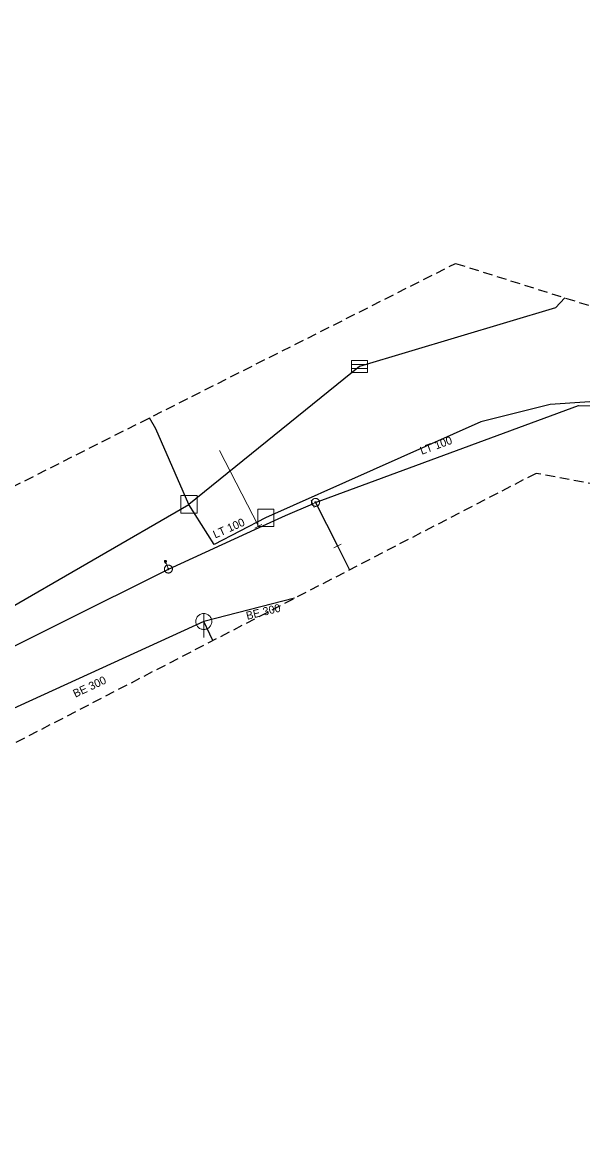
# Model space of a CAD drawing. Extents: x -688691 to -688449, y -974248 to -973966.
# Drawn here: x -688619.4 to -688549.3, y -974104.2 to -973965.6 of the extents above; entities that cross this region are included whole.
import ezdxf

# ---------------------------------------------------------------- set-up
doc = ezdxf.new("R2010")
doc.units = 0
doc.header["$LTSCALE"] = 0.4
doc.linetypes.add('MEDIUM_DASHED', pattern=[4.5, 3, -1.5])
for name, color, linetype, lineweight in [('1', 7, 'MEDIUM_DASHED', 25), ('13', 7, 'Continuous', 13), ('14', 7, 'Continuous', 25), ('17', 7, 'Continuous', 25), ('22', 7, 'Continuous', 13), ('34', 7, 'Continuous', 13), ('47', 7, 'Continuous', 13), ('9', 7, 'Continuous', 13)]:
    doc.layers.add(name, color=color, linetype=linetype, lineweight=lineweight)

msp = doc.modelspace()

# ---------------------------------------------------------------- linework, layer by layer
at = {"layer": '1'}
msp.add_lwpolyline([(-688492.642, -974007.422), (-688474.778, -973965.553), (-688449.099, -973975.602), (-688472.545, -974030.309), (-688492.642, -974033.659), (-688555.165, -974021.936), (-688650.066, -974071.061), (-688624.387, -974128.002), (-688613.222, -974120.745), (-688593.125, -974162.055), (-688604.29, -974165.404), (-688581.96, -974212.855), (-688565.213, -974206.156), (-688558.514, -974230.719), (-688607.64, -974248.024), (-688622.154, -974231.277), (-688607.64, -974225.136), (-688626.62, -974194.433), (-688691.376, -974059.338), (-688565.213, -973995.698), (-688544, -974002.397)], close=True, dxfattribs=at)
at = {"layer": '13'}
msp.add_line((-688589.863, -974028.551), (-688594.744, -974019.082), dxfattribs=at)
at = {"layer": '14'}
for p, q in [((-688577.23, -974008.592), (-688598.575, -974025.813)), ((-688658.556, -974060.52), (-688598.575, -974025.813)), ((-688585.339, -974037.555), (-688596.688, -974040.453)), ((-688596.688, -974040.453), (-688625, -974053.399)), ((-688595.545, -974042.839), (-688596.688, -974040.453))]:
    msp.add_line(p, q, dxfattribs=at)
at = {"layer": '14', "lineweight": 13}
for p, q in [((-688583.081, -974025.74), (-688582.724, -974025.561)), ((-688589.78, -974028.709), (-688589.863, -974028.551)), ((-688601.114, -974033.895), (-688601.489, -974032.939))]:
    msp.add_line(p, q, dxfattribs=at)
at = {"layer": '14'}
for points in [[(-688551.583, -974000.003), (-688552.727, -974001.266), (-688577.23, -974008.592)], [(-688544.118, -974012.713), (-688553.402, -974013.335), (-688562.069, -974015.498), (-688588.977, -974027.483)], [(-688598.575, -974025.813), (-688602.697, -974016.388), (-688603.455, -974014.989)], [(-688588.977, -974027.483), (-688595.407, -974030.817), (-688598.575, -974025.813)]]:
    msp.add_lwpolyline(points, dxfattribs=at)
at = {"layer": '17'}
for p, q in [((-688582.724, -974025.561), (-688579.989, -974031.009)), ((-688579.989, -974031.009), (-688578.486, -974034.008))]:
    msp.add_line(p, q, dxfattribs=at)
for points in [[(-688582.724, -974025.561), (-688549.875, -974013.454), (-688546.964, -974013.527)], [(-688601.114, -974033.895), (-688589.78, -974028.709), (-688586.478, -974027.199), (-688583.081, -974025.74)], [(-688652.327, -974058.754), (-688641.42, -974053.987), (-688601.114, -974033.895)]]:
    msp.add_lwpolyline(points, dxfattribs=at)
at = {"layer": '22'}
for p, q in [((-688578.241, -974008.335), (-688576.241, -974008.335)), ((-688578.241, -974008.835), (-688576.241, -974008.835)), ((-688596.688, -974042.453), (-688596.687, -974039.453))]:
    msp.add_line(p, q, dxfattribs=at)
for points in [[(-688578.241, -974007.835), (-688576.241, -974007.835), (-688576.241, -974009.335), (-688578.241, -974009.335)], [(-688599.554, -974024.723), (-688597.522, -974024.723), (-688597.522, -974026.916), (-688599.554, -974026.916)], [(-688589.956, -974026.393), (-688587.924, -974026.393), (-688587.924, -974028.586), (-688589.956, -974028.586)], [(-688595.688, -974040.453), (-688595.693, -974040.344), (-688595.711, -974040.236), (-688595.741, -974040.13), (-688595.781, -974040.029), (-688595.833, -974039.932), (-688595.895, -974039.842), (-688595.967, -974039.759), (-688596.047, -974039.685), (-688596.135, -974039.619), (-688596.229, -974039.564), (-688596.329, -974039.519), (-688596.434, -974039.486), (-688596.541, -974039.464), (-688596.65, -974039.454), (-688596.76, -974039.456), (-688596.868, -974039.47), (-688596.975, -974039.495), (-688597.078, -974039.532), (-688597.176, -974039.581), (-688597.268, -974039.639), (-688597.354, -974039.708), (-688597.431, -974039.785), (-688597.5, -974039.871), (-688597.559, -974039.963), (-688597.607, -974040.061), (-688597.644, -974040.164), (-688597.67, -974040.271), (-688597.684, -974040.379), (-688597.687, -974040.489), (-688597.677, -974040.598), (-688597.656, -974040.705), (-688597.622, -974040.809), (-688597.578, -974040.909), (-688597.523, -974041.004), (-688597.457, -974041.092), (-688597.383, -974041.172), (-688597.3, -974041.244), (-688597.21, -974041.306), (-688597.114, -974041.358), (-688597.012, -974041.399), (-688596.907, -974041.429), (-688596.799, -974041.447), (-688596.689, -974041.453), (-688596.58, -974041.447), (-688596.472, -974041.429), (-688596.367, -974041.4), (-688596.265, -974041.359), (-688596.168, -974041.307), (-688596.078, -974041.245), (-688595.995, -974041.174), (-688595.92, -974041.094), (-688595.855, -974041.006), (-688595.799, -974040.912), (-688595.755, -974040.812), (-688595.721, -974040.708), (-688595.699, -974040.6), (-688595.689, -974040.491)]]:
    msp.add_lwpolyline(points, close=True, dxfattribs=at)
at = {"layer": '34'}
for p, q in [((-688583.28, -974025.281), (-688582.882, -974026.198)), ((-688590.305, -974028.783), (-688589.419, -974028.319)), ((-688579.542, -974030.784), (-688580.436, -974031.232))]:
    msp.add_line(p, q, dxfattribs=at)
at = {"layer": '47'}
for points in [[(-688582.265, -974025.361), (-688582.288, -974025.315), (-688582.316, -974025.27), (-688582.349, -974025.23), (-688582.385, -974025.192), (-688582.426, -974025.159), (-688582.47, -974025.13), (-688582.516, -974025.106), (-688582.565, -974025.087), (-688582.615, -974025.073), (-688582.667, -974025.064), (-688582.719, -974025.06), (-688582.771, -974025.063), (-688582.823, -974025.071), (-688582.874, -974025.084), (-688582.923, -974025.102), (-688582.969, -974025.125), (-688583.014, -974025.153), (-688583.055, -974025.186), (-688583.092, -974025.222), (-688583.125, -974025.263), (-688583.154, -974025.307), (-688583.178, -974025.354), (-688583.198, -974025.402), (-688583.212, -974025.452), (-688583.22, -974025.504), (-688583.224, -974025.556), (-688583.221, -974025.609), (-688583.213, -974025.66), (-688583.2, -974025.711), (-688583.182, -974025.76), (-688583.159, -974025.806), (-688583.131, -974025.851), (-688583.098, -974025.892), (-688583.062, -974025.929), (-688583.021, -974025.962), (-688582.978, -974025.991), (-688582.931, -974026.016), (-688582.883, -974026.035), (-688582.832, -974026.049), (-688582.78, -974026.057), (-688582.728, -974026.061), (-688582.676, -974026.059), (-688582.624, -974026.05), (-688582.573, -974026.037), (-688582.524, -974026.019), (-688582.478, -974025.996), (-688582.433, -974025.968), (-688582.393, -974025.936), (-688582.355, -974025.899), (-688582.322, -974025.858), (-688582.293, -974025.815), (-688582.269, -974025.769), (-688582.25, -974025.72), (-688582.236, -974025.669), (-688582.227, -974025.617), (-688582.223, -974025.565), (-688582.226, -974025.514), (-688582.234, -974025.461), (-688582.247, -974025.41)], [(-688582.648, -974025.528), (-688582.652, -974025.52), (-688582.657, -974025.513), (-688582.662, -974025.507), (-688582.668, -974025.5), (-688582.675, -974025.495), (-688582.682, -974025.49), (-688582.689, -974025.486), (-688582.697, -974025.483), (-688582.706, -974025.481), (-688582.714, -974025.479), (-688582.723, -974025.479), (-688582.732, -974025.479), (-688582.74, -974025.48), (-688582.748, -974025.482), (-688582.756, -974025.485), (-688582.764, -974025.489), (-688582.771, -974025.494), (-688582.777, -974025.499), (-688582.784, -974025.505), (-688582.789, -974025.512), (-688582.794, -974025.519), (-688582.798, -974025.526), (-688582.801, -974025.534), (-688582.804, -974025.543), (-688582.805, -974025.551), (-688582.805, -974025.56), (-688582.805, -974025.569), (-688582.804, -974025.577), (-688582.802, -974025.585), (-688582.799, -974025.593), (-688582.795, -974025.601), (-688582.79, -974025.608), (-688582.785, -974025.614), (-688582.779, -974025.621), (-688582.772, -974025.626), (-688582.766, -974025.631), (-688582.758, -974025.635), (-688582.75, -974025.638), (-688582.741, -974025.641), (-688582.733, -974025.642), (-688582.724, -974025.642), (-688582.715, -974025.642), (-688582.707, -974025.641), (-688582.699, -974025.639), (-688582.691, -974025.636), (-688582.683, -974025.632), (-688582.676, -974025.627), (-688582.67, -974025.622), (-688582.663, -974025.616), (-688582.658, -974025.609), (-688582.653, -974025.603), (-688582.649, -974025.595), (-688582.646, -974025.587), (-688582.644, -974025.578), (-688582.642, -974025.57), (-688582.642, -974025.561), (-688582.642, -974025.552), (-688582.643, -974025.544), (-688582.645, -974025.536)], [(-688600.662, -974033.679), (-688600.688, -974033.633), (-688600.717, -974033.59), (-688600.751, -974033.551), (-688600.789, -974033.514), (-688600.831, -974033.482), (-688600.876, -974033.455), (-688600.923, -974033.433), (-688600.972, -974033.416), (-688601.023, -974033.403), (-688601.075, -974033.396), (-688601.127, -974033.395), (-688601.179, -974033.4), (-688601.231, -974033.408), (-688601.281, -974033.424), (-688601.329, -974033.443), (-688601.375, -974033.469), (-688601.418, -974033.498), (-688601.458, -974033.533), (-688601.494, -974033.57), (-688601.526, -974033.612), (-688601.553, -974033.657), (-688601.576, -974033.704), (-688601.593, -974033.754), (-688601.606, -974033.804), (-688601.612, -974033.856), (-688601.613, -974033.908), (-688601.609, -974033.961), (-688601.6, -974034.012), (-688601.584, -974034.062), (-688601.565, -974034.11), (-688601.539, -974034.156), (-688601.51, -974034.199), (-688601.476, -974034.24), (-688601.438, -974034.275), (-688601.396, -974034.307), (-688601.352, -974034.334), (-688601.305, -974034.357), (-688601.255, -974034.375), (-688601.204, -974034.387), (-688601.152, -974034.393), (-688601.1, -974034.394), (-688601.048, -974034.391), (-688600.996, -974034.381), (-688600.946, -974034.365), (-688600.898, -974034.346), (-688600.852, -974034.32), (-688600.809, -974034.291), (-688600.769, -974034.258), (-688600.733, -974034.219), (-688600.701, -974034.177), (-688600.674, -974034.133), (-688600.652, -974034.086), (-688600.634, -974034.037), (-688600.622, -974033.985), (-688600.615, -974033.933), (-688600.614, -974033.881), (-688600.618, -974033.829), (-688600.627, -974033.777), (-688600.643, -974033.727)], [(-688601.04, -974033.859), (-688601.043, -974033.851), (-688601.049, -974033.845), (-688601.054, -974033.838), (-688601.06, -974033.832), (-688601.067, -974033.827), (-688601.075, -974033.823), (-688601.082, -974033.819), (-688601.09, -974033.816), (-688601.099, -974033.814), (-688601.107, -974033.813), (-688601.116, -974033.813), (-688601.125, -974033.813), (-688601.133, -974033.815), (-688601.141, -974033.817), (-688601.149, -974033.821), (-688601.157, -974033.824), (-688601.163, -974033.83), (-688601.17, -974033.835), (-688601.176, -974033.841), (-688601.181, -974033.848), (-688601.185, -974033.856), (-688601.189, -974033.863), (-688601.192, -974033.871), (-688601.195, -974033.88), (-688601.195, -974033.888), (-688601.195, -974033.897), (-688601.195, -974033.906), (-688601.193, -974033.914), (-688601.191, -974033.922), (-688601.187, -974033.93), (-688601.184, -974033.938), (-688601.178, -974033.944), (-688601.173, -974033.951), (-688601.167, -974033.957), (-688601.16, -974033.962), (-688601.153, -974033.967), (-688601.145, -974033.97), (-688601.137, -974033.973), (-688601.128, -974033.976), (-688601.12, -974033.976), (-688601.111, -974033.976), (-688601.102, -974033.976), (-688601.094, -974033.974), (-688601.086, -974033.972), (-688601.078, -974033.968), (-688601.07, -974033.965), (-688601.064, -974033.959), (-688601.057, -974033.954), (-688601.051, -974033.948), (-688601.046, -974033.941), (-688601.041, -974033.934), (-688601.038, -974033.926), (-688601.035, -974033.918), (-688601.033, -974033.909), (-688601.032, -974033.901), (-688601.032, -974033.892), (-688601.032, -974033.883), (-688601.034, -974033.875), (-688601.036, -974033.867)]]:
    msp.add_lwpolyline(points, close=True, dxfattribs=at)
at = {"layer": '9'}
msp.add_line((-688601.49, -974033.066), (-688601.49, -974033.191), dxfattribs=at)
for points in [[(-688601.616, -974032.938), (-688601.615, -974032.951), (-688601.613, -974032.964), (-688601.61, -974032.977), (-688601.605, -974032.989), (-688601.599, -974033.001), (-688601.592, -974033.012), (-688601.584, -974033.022), (-688601.574, -974033.032), (-688601.564, -974033.04), (-688601.553, -974033.047), (-688601.541, -974033.053), (-688601.529, -974033.058), (-688601.516, -974033.061), (-688601.503, -974033.063), (-688601.49, -974033.066), (-688601.477, -974033.065), (-688601.464, -974033.063), (-688601.451, -974033.06), (-688601.439, -974033.055), (-688601.427, -974033.049), (-688601.416, -974033.042), (-688601.406, -974033.034), (-688601.396, -974033.024), (-688601.388, -974033.014), (-688601.381, -974033.003), (-688601.375, -974032.991), (-688601.37, -974032.979), (-688601.367, -974032.966), (-688601.365, -974032.953), (-688601.363, -974032.94), (-688601.364, -974032.927), (-688601.366, -974032.914), (-688601.369, -974032.901), (-688601.374, -974032.889), (-688601.38, -974032.877), (-688601.387, -974032.866), (-688601.395, -974032.856), (-688601.405, -974032.846), (-688601.415, -974032.838), (-688601.426, -974032.831), (-688601.438, -974032.825), (-688601.45, -974032.82), (-688601.463, -974032.817), (-688601.476, -974032.815), (-688601.489, -974032.813), (-688601.502, -974032.813), (-688601.515, -974032.815), (-688601.528, -974032.818), (-688601.54, -974032.823), (-688601.552, -974032.829), (-688601.563, -974032.836), (-688601.573, -974032.844), (-688601.583, -974032.854), (-688601.591, -974032.864), (-688601.598, -974032.875), (-688601.604, -974032.887), (-688601.609, -974032.899), (-688601.612, -974032.912), (-688601.614, -974032.925)], [(-688601.596, -974032.938), (-688601.596, -974032.949), (-688601.594, -974032.96), (-688601.591, -974032.971), (-688601.587, -974032.981), (-688601.582, -974032.991), (-688601.576, -974033), (-688601.569, -974033.009), (-688601.561, -974033.017), (-688601.552, -974033.024), (-688601.543, -974033.03), (-688601.533, -974033.035), (-688601.523, -974033.039), (-688601.512, -974033.042), (-688601.501, -974033.044), (-688601.49, -974033.044), (-688601.479, -974033.046), (-688601.468, -974033.044), (-688601.457, -974033.041), (-688601.447, -974033.037), (-688601.437, -974033.032), (-688601.428, -974033.026), (-688601.419, -974033.019), (-688601.411, -974033.011), (-688601.404, -974033.002), (-688601.398, -974032.993), (-688601.393, -974032.983), (-688601.389, -974032.973), (-688601.386, -974032.962), (-688601.384, -974032.951), (-688601.383, -974032.94), (-688601.383, -974032.929), (-688601.385, -974032.918), (-688601.388, -974032.907), (-688601.392, -974032.897), (-688601.397, -974032.887), (-688601.403, -974032.878), (-688601.41, -974032.869), (-688601.418, -974032.861), (-688601.427, -974032.854), (-688601.436, -974032.848), (-688601.446, -974032.843), (-688601.456, -974032.839), (-688601.467, -974032.836), (-688601.478, -974032.834), (-688601.489, -974032.833), (-688601.5, -974032.832), (-688601.511, -974032.834), (-688601.522, -974032.837), (-688601.532, -974032.841), (-688601.542, -974032.846), (-688601.551, -974032.852), (-688601.56, -974032.859), (-688601.568, -974032.867), (-688601.575, -974032.876), (-688601.581, -974032.885), (-688601.586, -974032.895), (-688601.59, -974032.905), (-688601.593, -974032.916), (-688601.595, -974032.927)], [(-688601.577, -974032.938), (-688601.576, -974032.947), (-688601.575, -974032.956), (-688601.572, -974032.965), (-688601.569, -974032.973), (-688601.565, -974032.981), (-688601.56, -974032.989), (-688601.554, -974032.996), (-688601.548, -974033.002), (-688601.541, -974033.008), (-688601.533, -974033.013), (-688601.525, -974033.017), (-688601.517, -974033.02), (-688601.508, -974033.023), (-688601.499, -974033.024), (-688601.49, -974033.027), (-688601.481, -974033.026), (-688601.472, -974033.025), (-688601.463, -974033.022), (-688601.455, -974033.019), (-688601.447, -974033.015), (-688601.439, -974033.01), (-688601.432, -974033.004), (-688601.426, -974032.998), (-688601.42, -974032.991), (-688601.415, -974032.983), (-688601.411, -974032.975), (-688601.408, -974032.967), (-688601.405, -974032.958), (-688601.404, -974032.949), (-688601.402, -974032.94), (-688601.403, -974032.931), (-688601.404, -974032.922), (-688601.407, -974032.913), (-688601.41, -974032.905), (-688601.414, -974032.897), (-688601.419, -974032.889), (-688601.425, -974032.882), (-688601.431, -974032.876), (-688601.438, -974032.87), (-688601.446, -974032.865), (-688601.454, -974032.861), (-688601.462, -974032.858), (-688601.471, -974032.855), (-688601.48, -974032.854), (-688601.489, -974032.852), (-688601.498, -974032.852), (-688601.507, -974032.853), (-688601.516, -974032.856), (-688601.524, -974032.859), (-688601.532, -974032.863), (-688601.54, -974032.868), (-688601.547, -974032.874), (-688601.553, -974032.88), (-688601.559, -974032.887), (-688601.564, -974032.895), (-688601.568, -974032.903), (-688601.571, -974032.911), (-688601.574, -974032.92), (-688601.575, -974032.929)], [(-688601.557, -974032.938), (-688601.557, -974032.945), (-688601.555, -974032.952), (-688601.554, -974032.959), (-688601.551, -974032.965), (-688601.548, -974032.971), (-688601.544, -974032.977), (-688601.54, -974032.983), (-688601.535, -974032.988), (-688601.529, -974032.992), (-688601.523, -974032.996), (-688601.517, -974032.999), (-688601.511, -974033.002), (-688601.504, -974033.003), (-688601.497, -974033.005), (-688601.49, -974033.005), (-688601.483, -974033.007), (-688601.476, -974033.005), (-688601.469, -974033.004), (-688601.463, -974033.001), (-688601.456, -974032.998), (-688601.451, -974032.994), (-688601.445, -974032.99), (-688601.44, -974032.985), (-688601.436, -974032.979), (-688601.432, -974032.973), (-688601.429, -974032.967), (-688601.426, -974032.961), (-688601.424, -974032.954), (-688601.423, -974032.947), (-688601.422, -974032.94), (-688601.422, -974032.933), (-688601.423, -974032.926), (-688601.425, -974032.919), (-688601.428, -974032.913), (-688601.431, -974032.906), (-688601.435, -974032.901), (-688601.439, -974032.895), (-688601.444, -974032.89), (-688601.45, -974032.886), (-688601.455, -974032.882), (-688601.462, -974032.879), (-688601.468, -974032.876), (-688601.475, -974032.874), (-688601.482, -974032.873), (-688601.489, -974032.872), (-688601.496, -974032.871), (-688601.503, -974032.872), (-688601.51, -974032.874), (-688601.516, -974032.877), (-688601.522, -974032.88), (-688601.528, -974032.884), (-688601.534, -974032.888), (-688601.539, -974032.893), (-688601.543, -974032.899), (-688601.547, -974032.904), (-688601.55, -974032.911), (-688601.553, -974032.917), (-688601.554, -974032.924), (-688601.556, -974032.931)], [(-688601.537, -974032.938), (-688601.537, -974032.943), (-688601.536, -974032.948), (-688601.535, -974032.953), (-688601.533, -974032.957), (-688601.531, -974032.962), (-688601.528, -974032.966), (-688601.525, -974032.969), (-688601.521, -974032.973), (-688601.518, -974032.976), (-688601.514, -974032.979), (-688601.509, -974032.981), (-688601.505, -974032.983), (-688601.5, -974032.984), (-688601.495, -974032.985), (-688601.49, -974032.985), (-688601.485, -974032.987), (-688601.48, -974032.986), (-688601.475, -974032.985), (-688601.471, -974032.983), (-688601.466, -974032.981), (-688601.462, -974032.978), (-688601.458, -974032.975), (-688601.455, -974032.971), (-688601.452, -974032.968), (-688601.449, -974032.964), (-688601.447, -974032.959), (-688601.445, -974032.955), (-688601.444, -974032.95), (-688601.443, -974032.945), (-688601.443, -974032.94), (-688601.442, -974032.935), (-688601.443, -974032.93), (-688601.444, -974032.925), (-688601.446, -974032.921), (-688601.448, -974032.916), (-688601.451, -974032.912), (-688601.454, -974032.908), (-688601.457, -974032.905), (-688601.461, -974032.902), (-688601.465, -974032.899), (-688601.47, -974032.897), (-688601.474, -974032.895), (-688601.479, -974032.894), (-688601.484, -974032.893), (-688601.489, -974032.892), (-688601.494, -974032.891), (-688601.499, -974032.892), (-688601.504, -974032.893), (-688601.508, -974032.895), (-688601.513, -974032.897), (-688601.517, -974032.9), (-688601.52, -974032.903), (-688601.524, -974032.906), (-688601.527, -974032.91), (-688601.53, -974032.914), (-688601.532, -974032.919), (-688601.534, -974032.923), (-688601.535, -974032.928), (-688601.536, -974032.933)], [(-688601.517, -974032.938), (-688601.517, -974032.941), (-688601.517, -974032.944), (-688601.516, -974032.946), (-688601.515, -974032.949), (-688601.514, -974032.952), (-688601.512, -974032.954), (-688601.51, -974032.956), (-688601.508, -974032.958), (-688601.506, -974032.96), (-688601.504, -974032.962), (-688601.501, -974032.963), (-688601.498, -974032.964), (-688601.496, -974032.965), (-688601.493, -974032.965), (-688601.49, -974032.965), (-688601.487, -974032.967), (-688601.484, -974032.967), (-688601.481, -974032.966), (-688601.479, -974032.965), (-688601.476, -974032.964), (-688601.474, -974032.962), (-688601.471, -974032.96), (-688601.469, -974032.958), (-688601.468, -974032.956), (-688601.466, -974032.954), (-688601.465, -974032.951), (-688601.464, -974032.948), (-688601.463, -974032.946), (-688601.463, -974032.943), (-688601.461, -974032.94), (-688601.462, -974032.937), (-688601.462, -974032.934), (-688601.463, -974032.931), (-688601.464, -974032.929), (-688601.465, -974032.926), (-688601.467, -974032.924), (-688601.468, -974032.921), (-688601.47, -974032.919), (-688601.473, -974032.918), (-688601.475, -974032.916), (-688601.478, -974032.915), (-688601.48, -974032.914), (-688601.483, -974032.913), (-688601.486, -974032.913), (-688601.489, -974032.911), (-688601.492, -974032.911), (-688601.495, -974032.911), (-688601.497, -974032.912), (-688601.5, -974032.913), (-688601.503, -974032.914), (-688601.505, -974032.916), (-688601.507, -974032.917), (-688601.509, -974032.919), (-688601.511, -974032.922), (-688601.513, -974032.924), (-688601.514, -974032.927), (-688601.515, -974032.929), (-688601.516, -974032.932), (-688601.516, -974032.935)], [(-688601.498, -974032.938), (-688601.498, -974032.939), (-688601.498, -974032.94), (-688601.497, -974032.94), (-688601.497, -974032.941), (-688601.497, -974032.942), (-688601.496, -974032.943), (-688601.496, -974032.943), (-688601.495, -974032.944), (-688601.495, -974032.944), (-688601.494, -974032.945), (-688601.493, -974032.945), (-688601.492, -974032.945), (-688601.492, -974032.946), (-688601.491, -974032.946), (-688601.49, -974032.946), (-688601.489, -974032.947), (-688601.488, -974032.947), (-688601.488, -974032.947), (-688601.487, -974032.947), (-688601.486, -974032.947), (-688601.485, -974032.946), (-688601.485, -974032.946), (-688601.484, -974032.945), (-688601.484, -974032.945), (-688601.483, -974032.944), (-688601.483, -974032.943), (-688601.482, -974032.942), (-688601.482, -974032.942), (-688601.482, -974032.941), (-688601.481, -974032.94), (-688601.481, -974032.939), (-688601.481, -974032.938), (-688601.481, -974032.938), (-688601.482, -974032.937), (-688601.482, -974032.936), (-688601.483, -974032.935), (-688601.483, -974032.935), (-688601.484, -974032.934), (-688601.484, -974032.934), (-688601.485, -974032.933), (-688601.486, -974032.933), (-688601.487, -974032.932), (-688601.487, -974032.932), (-688601.488, -974032.932), (-688601.489, -974032.931), (-688601.49, -974032.931), (-688601.491, -974032.93), (-688601.491, -974032.93), (-688601.492, -974032.931), (-688601.493, -974032.931), (-688601.494, -974032.932), (-688601.494, -974032.932), (-688601.495, -974032.933), (-688601.495, -974032.933), (-688601.496, -974032.934), (-688601.496, -974032.935), (-688601.496, -974032.936), (-688601.497, -974032.936), (-688601.497, -974032.937)]]:
    msp.add_lwpolyline(points, close=True, dxfattribs=at)
msp.add_lwpolyline([(-688601.459, -974033.157), (-688601.49, -974033.191), (-688601.521, -974033.155)], dxfattribs=at)

# ---------------------------------------------------------------- texts
at = {"layer": '1'}
for s, rotation, p in [('LT 100', 20, (-688569.455, -974019.62)), ('LT 100', 24, (-688595.266, -974030.09)), ('BE 300', 14, (-688591.264, -974040.249)), ('BE 300', 25, (-688612.746, -974049.979))]:
    msp.add_text(s, height=1, rotation=rotation, dxfattribs=at).set_placement(p)

doc.saveas('drawing.dxf')
